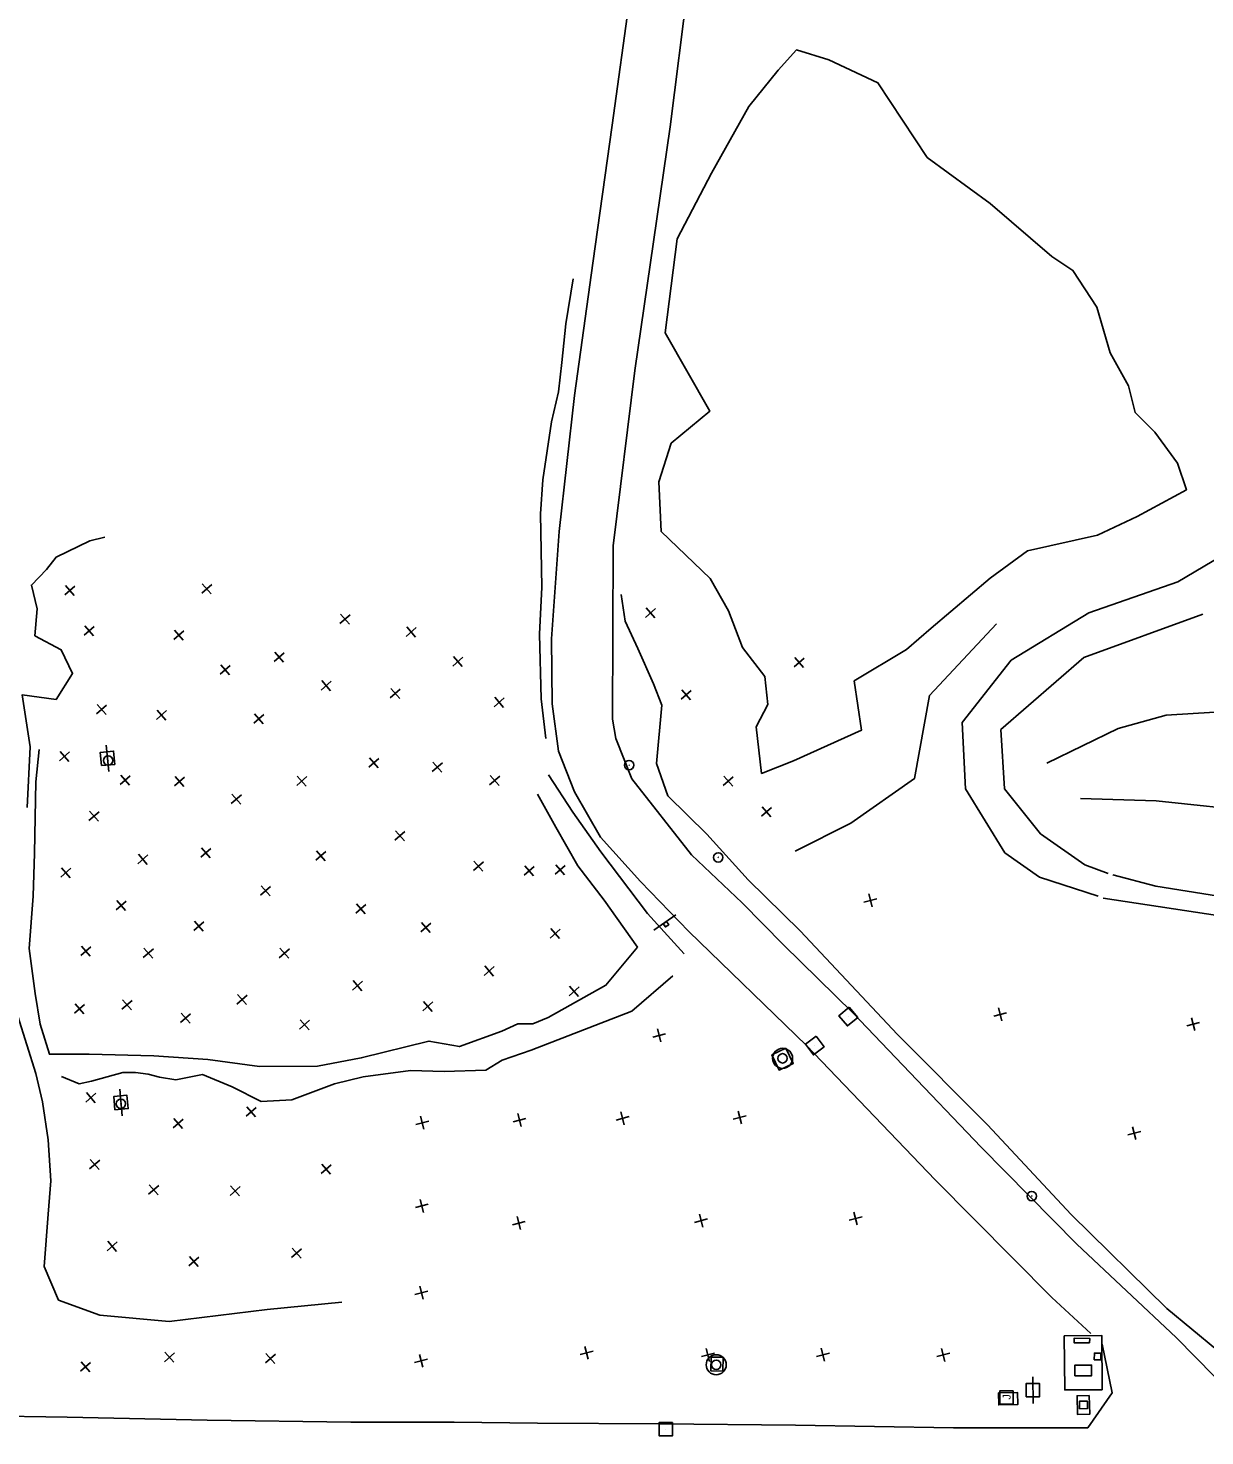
# Model space of a CAD drawing. Extents: x 4711259 to 4716401, y 890074 to 892728.
# Drawn here: x 4712145 to 4712586, y 891911 to 892439 of the extents above; entities that cross this region are included whole.
import ezdxf

# ---------------------------------------------------------------- set-up
doc = ezdxf.new("R2010")
doc.units = 0
for name, color, linetype in [('E_HY_STORM_Inlet', 7, 'Continuous'), ('E_HY_STORM_MH', 7, 'Continuous'), ('E_RDWY_ROAD_EdgeAsph', 7, 'Continuous'), ('E_RDWY_ROAD_EdgeConc', 7, 'Continuous'), ('E_RDWY_ROAD_EdgeGravel', 7, 'Continuous'), ('E_TERR_DTM_BrkLines', 7, 'Continuous'), ('E_TERR_DTM_RandomPt', 7, 'Continuous'), ('E_TRAF_SIGN_PrivateSign', 7, 'Continuous'), ('E_UTIL_ELEC_GENERAL', 7, 'Continuous'), ('E_UTIL_ELEC_POLE', 7, 'Continuous'), ('E_UTIL_MISC_General', 7, 'Continuous')]:
    doc.layers.add(name, color=color, linetype=linetype)

msp = doc.modelspace()

# ---------------------------------------------------------------- linework, layer by layer
at = {"layer": 'E_HY_STORM_Inlet'}
for p, q in [((4712452.77, 892068.62), (4712452.77, 892068.62)), ((4712440.17, 892057.77), (4712440.17, 892057.77)), ((4712384.34, 891913.98), (4712384.34, 891913.98))]:
    msp.add_line(p, q, dxfattribs=at)
for points in [[(4712453.09, 892072.14), (4712456.29, 892068.3), (4712452.45, 892065.1), (4712449.25, 892068.94)], [(4712440.65, 892061.28), (4712443.68, 892057.3), (4712439.7, 892054.27), (4712436.67, 892058.25)], [(4712386.81, 891916.51), (4712386.87, 891911.51), (4712381.87, 891911.45), (4712381.81, 891916.45)]]:
    msp.add_lwpolyline(points, close=True, dxfattribs=at)
at = {"layer": 'E_HY_STORM_MH'}
for centre, radius in [((4712428.12, 892052.97), 3.75), ((4712428.12, 892052.97), 1.76), ((4712403.22, 891938.11), 3.75), ((4712403.22, 891938.11), 1.76)]:
    msp.add_circle(centre, radius, dxfattribs=at)
at = {"layer": 'E_RDWY_ROAD_EdgeAsph'}
for points in [[(4712392.98, 892100.57), (4712374.85, 892119.26), (4712359.79, 892135.87), (4712350.09, 892152.92), (4712344.08, 892168.12), (4712341.64, 892185.83), (4712341.4, 892210.27), (4712344.38, 892250.53), (4712350.11, 892301.49), (4712356.98, 892351.1), (4712364.23, 892402.81), (4712370.85, 892450.92), (4712379.56, 892517.79), (4712388.22, 892587.46), (4712389.9, 892600.3)], [(4712411.53, 892596.72), (4712406.74, 892563.84), (4712398.3, 892499.3), (4712392.59, 892454.74), (4712385.98, 892402.12), (4712379.7, 892359.09), (4712372.74, 892310.83), (4712364.63, 892245.09), (4712364.34, 892180.15), (4712365.6, 892172.88), (4712371.63, 892157.7), (4712393.89, 892129.21), (4712412.91, 892111.29)], [(4712611.49, 891911.96), (4712575.66, 891948.29), (4712538.41, 891983.36), (4712502.63, 892019.7), (4712473.24, 892050.46), (4712454.51, 892069.97), (4712428.44, 892095.53), (4712412.91, 892111.29)], [(4712392.98, 892100.57), (4712437.09, 892057.82)], [(4712437.09, 892057.82), (4712485.27, 892007.48), (4712529.12, 891963.34), (4712543.72, 891949.78)], [(4712547.94, 891945.86), (4712551.69, 891927.6), (4712542.54, 891914.41), (4712492.24, 891914.44), (4712432.99, 891915.41), (4712382.1, 891915.95)], [(4712266.21, 891916.53), (4712212.37, 891917.36), (4712159.79, 891918.41), (4712127.55, 891918.93)], [(4712266.21, 891916.53), (4712304.99, 891916.54)], [(4712382.1, 891915.95), (4712336.14, 891916.18), (4712304.99, 891916.54)]]:
    msp.add_lwpolyline(points, dxfattribs=at)
at = {"layer": 'E_RDWY_ROAD_EdgeConc'}
for points in [[(4712429.38, 892056.77), (4712432.09, 892051.05), (4712426.81, 892048.55), (4712424.1, 892054.27)], [(4712533.77, 891949), (4712533.91, 891928.64), (4712547.95, 891928.74), (4712547.8, 891949.1)], [(4712401.36, 891940.99), (4712401.26, 891935.77), (4712405.72, 891935.69), (4712405.82, 891940.91)], [(4712509.11, 891927.56), (4712509.16, 891923.05), (4712516.3, 891923.14), (4712516.24, 891927.65)], [(4712543.13, 891926.59), (4712543.28, 891919.56), (4712538.68, 891919.47), (4712538.54, 891926.5)]]:
    msp.add_lwpolyline(points, close=True, dxfattribs=at)
at = {"layer": 'E_RDWY_ROAD_EdgeGravel'}
for points in [[(4712651.98, 892011.81), (4712651.97, 892011.81), (4712639.35, 892032.8), (4712635.99, 892051.36), (4712635.99, 892063.8), (4712634.48, 892083.04), (4712623.92, 892102.34), (4712600.26, 892112.35), (4712568.04, 892117.52), (4712551.95, 892121.72)], [(4712548.39, 892113.07), (4712595.33, 892105.89), (4712618.97, 892096.38), (4712626.83, 892078.05), (4712627.02, 892062.56), (4712629.02, 892036.67), (4712637.35, 892015.83), (4712646.12, 892006.34)]]:
    msp.add_lwpolyline(points, dxfattribs=at)
at = {"layer": 'E_TERR_DTM_BrkLines'}
for points in [[(4712432.18, 892164.48), (4712420.26, 892159.79), (4712418.21, 892177.21), (4712422.52, 892185.67), (4712421.46, 892196.16), (4712413.1, 892206.99), (4712407.81, 892220.7), (4712400.91, 892232.82), (4712382.63, 892250.5), (4712381.72, 892269.09), (4712386.27, 892283.53), (4712400.79, 892295.52), (4712384.12, 892324.98), (4712388.62, 892360.17), (4712401.49, 892384.79), (4712415.49, 892409.75), (4712426.49, 892423.39), (4712433.37, 892430.99), (4712445.46, 892427.29), (4712463.85, 892418.72), (4712482.3, 892390.69), (4712505.97, 892373.38), (4712529.14, 892353.61), (4712537.01, 892348.34), (4712545.9, 892334.57), (4712551, 892317.51), (4712557.88, 892305.06), (4712560.31, 892295.13), (4712567.68, 892287.65), (4712576.27, 892276.05), (4712579.58, 892266.1), (4712561.12, 892256.12), (4712546.16, 892249.15), (4712519.99, 892243.18), (4712505.94, 892232.97), (4712483.86, 892214.17), (4712474.6, 892206.24), (4712454.97, 892194.44), (4712457.7, 892175.97), (4712432.18, 892164.48)], [(4712339.29, 892172.92), (4712337.59, 892187.77), (4712336.93, 892211.95), (4712337.78, 892229.57), (4712337.36, 892257.07), (4712338.19, 892269.78), (4712341.39, 892291.6), (4712344.04, 892302.85), (4712345.27, 892313.87), (4712346.79, 892328.36), (4712349.57, 892345.14)], [(4712144.82, 892147.01), (4712145.96, 892169.74), (4712142.91, 892189.2), (4712155.65, 892187.47), (4712161.85, 892197.25), (4712157.58, 892206.17), (4712147.72, 892211.39), (4712148.62, 892221.53), (4712146.44, 892230.36), (4712152.12, 892236.19), (4712155.66, 892240.87), (4712168.35, 892246.91), (4712173.97, 892248.37)], [(4712546.45, 892113.77), (4712524.47, 892120.93), (4712511.44, 892130.07), (4712496.7, 892154.02), (4712495.5, 892178.83), (4712513.86, 892202.27), (4712543.01, 892220.01), (4712576.35, 892231.61), (4712592.62, 892241.19)], [(4712399.71, 892137), (4712385.06, 892151.32), (4712380.83, 892163.48), (4712382.85, 892185.31), (4712379.72, 892193.38), (4712373.83, 892206.65), (4712369.02, 892216.88), (4712367.53, 892226.88)], [(4712585.76, 892219.47), (4712541.13, 892203.22), (4712509.96, 892176.19), (4712511.32, 892154.06), (4712524.79, 892137.18), (4712541.41, 892125.46), (4712550.27, 892122.23)], [(4712432.87, 892130.6), (4712453.75, 892141.12), (4712477.58, 892157.87), (4712483.26, 892188.93), (4712508.39, 892215.83)], [(4712527.2, 892163.66), (4712554.02, 892176.64), (4712571.96, 892181.61), (4712608.43, 892183.92), (4712629.84, 892177.13), (4712683.46, 892182.87), (4712727.45, 892167.89), (4712767.53, 892172.83)], [(4712149.3, 892168.76), (4712148.1, 892156.57), (4712147.59, 892129.91), (4712147.08, 892113.77), (4712145.57, 892094.19), (4712147.76, 892077.26), (4712149.65, 892065.74), (4712153.15, 892054.51), (4712168.02, 892054.52), (4712192.37, 892053.88), (4712212.55, 892052.55), (4712231.9, 892049.97), (4712253.67, 892050.04), (4712270.1, 892053.12), (4712295.45, 892059.45), (4712306.89, 892057.35), (4712322.79, 892063.11), (4712328.83, 892065.88), (4712334.42, 892065.87), (4712340.26, 892068.34)], [(4712340.37, 892159.24), (4712349.51, 892145.22), (4712360, 892130.39), (4712377.4, 892107.24), (4712391.21, 892092.13)], [(4712373.74, 892094.64), (4712361.22, 892112.26), (4712351.36, 892125.16), (4712343.02, 892139.63), (4712336.22, 892152.01)], [(4712750.46, 892108.86), (4712730.1, 892125.9), (4712687.22, 892140.73), (4712641.38, 892141.46), (4712608.28, 892145.28), (4712568.27, 892149.46), (4712539.83, 892150.37)], [(4712619.1, 891920.49), (4712572.27, 891959.19), (4712536.3, 891994.41), (4712505.02, 892028.08), (4712471.23, 892061.89), (4712434.73, 892100.76), (4712415.26, 892119.86), (4712399.71, 892137)], [(4712373.74, 892094.64), (4712361.86, 892080.36), (4712340.26, 892068.34)], [(4712333.85, 892056.08), (4712371.6, 892070.68), (4712386.95, 892083.84)], [(4712262.78, 891961.59), (4712234.78, 891958.84), (4712198.06, 891954.35), (4712172.03, 891956.7), (4712156.6, 891962.35), (4712151.24, 891974.89), (4712152.67, 891994.51), (4712153.68, 892007.02), (4712152.63, 892022.38), (4712150.59, 892036.69), (4712148.04, 892047.33), (4712141.36, 892068.82)], [(4712333.85, 892056.08), (4712323.01, 892052.26), (4712316.85, 892048.5), (4712301.18, 892048.01), (4712288.53, 892048.35), (4712270.85, 892046.06), (4712260.09, 892043.47), (4712244.1, 892037.45), (4712232.63, 892036.82), (4712221.68, 892042.3), (4712210.6, 892046.9), (4712200.54, 892044.93), (4712194.43, 892045.91), (4712190.23, 892047.08), (4712185.46, 892047.61), (4712180.66, 892047.61), (4712168.93, 892044.46), (4712164.37, 892043.47), (4712157.7, 892046.18)]]:
    msp.add_lwpolyline(points, dxfattribs=at)
at = {"layer": 'E_TERR_DTM_RandomPt'}
for p, q in [((4712162.68, 892230.02), (4712158.92, 892226.73)), ((4712162.45, 892226.49), (4712159.15, 892230.25)), ((4712214.02, 892230.66), (4712210.26, 892227.36)), ((4712213.79, 892227.13), (4712210.5, 892230.89)), ((4712265.9, 892219.25), (4712262.13, 892215.96)), ((4712265.66, 892215.73), (4712262.37, 892219.49)), ((4712380.45, 892221.57), (4712376.68, 892218.28)), ((4712380.21, 892218.05), (4712376.92, 892221.81)), ((4712169.97, 892214.85), (4712166.2, 892211.56)), ((4712169.73, 892211.32), (4712166.44, 892215.08)), ((4712203.6, 892213.28), (4712199.84, 892209.99)), ((4712203.36, 892209.75), (4712200.07, 892213.51)), ((4712290.68, 892214.44), (4712286.91, 892211.15)), ((4712290.44, 892210.92), (4712287.15, 892214.68)), ((4712241.18, 892204.98), (4712237.41, 892201.69)), ((4712240.94, 892201.45), (4712237.65, 892205.22)), ((4712308.16, 892203.33), (4712304.4, 892200.04)), ((4712307.93, 892199.8), (4712304.64, 892203.57)), ((4712436.22, 892203.02), (4712432.45, 892199.73)), ((4712435.98, 892199.49), (4712432.69, 892203.26)), ((4712220.95, 892200.22), (4712217.18, 892196.93)), ((4712220.71, 892196.7), (4712217.42, 892200.46)), ((4712258.8, 892194.33), (4712255.04, 892191.04)), ((4712258.57, 892190.8), (4712255.28, 892194.56)), ((4712284.75, 892191.41), (4712280.98, 892188.12)), ((4712284.51, 892187.89), (4712281.22, 892191.65)), ((4712323.7, 892188.08), (4712319.94, 892184.79)), ((4712323.47, 892184.55), (4712320.17, 892188.32)), ((4712393.87, 892190.91), (4712390.11, 892187.62)), ((4712393.63, 892187.39), (4712390.34, 892191.15)), ((4712174.62, 892185.42), (4712170.86, 892182.12)), ((4712174.39, 892181.89), (4712171.09, 892185.65)), ((4712197.1, 892183.31), (4712193.34, 892180.01)), ((4712196.86, 892179.78), (4712193.57, 892183.54)), ((4712233.58, 892181.86), (4712229.81, 892178.57)), ((4712233.34, 892178.33), (4712230.05, 892182.09)), ((4712160.71, 892167.81), (4712156.94, 892164.52)), ((4712160.47, 892164.28), (4712157.18, 892168.05)), ((4712276.68, 892165.38), (4712272.91, 892162.09)), ((4712276.44, 892161.86), (4712273.15, 892165.62)), ((4712300.52, 892163.73), (4712296.76, 892160.44)), ((4712300.29, 892160.21), (4712297, 892163.97)), ((4712183.49, 892158.92), (4712179.73, 892155.63)), ((4712183.25, 892155.39), (4712179.96, 892159.16)), ((4712203.86, 892158.37), (4712200.1, 892155.08)), ((4712203.62, 892154.85), (4712200.33, 892158.61)), ((4712249.66, 892158.57), (4712245.89, 892155.28)), ((4712249.42, 892155.04), (4712246.13, 892158.81)), ((4712322.03, 892158.78), (4712318.26, 892155.48)), ((4712321.79, 892155.25), (4712318.5, 892159.01)), ((4712409.64, 892158.53), (4712405.88, 892155.24)), ((4712409.41, 892155.01), (4712406.12, 892158.77)), ((4712225.15, 892151.76), (4712221.38, 892148.47)), ((4712224.91, 892148.23), (4712221.62, 892151.99)), ((4712171.76, 892145.37), (4712168, 892142.08)), ((4712171.53, 892141.84), (4712168.24, 892145.61)), ((4712423.95, 892147), (4712420.19, 892143.71)), ((4712423.71, 892143.47), (4712420.42, 892147.23)), ((4712286.5, 892138.06), (4712282.73, 892134.77)), ((4712286.26, 892134.54), (4712282.97, 892138.3)), ((4712190.09, 892129.21), (4712186.33, 892125.92)), ((4712189.85, 892125.68), (4712186.56, 892129.45)), ((4712213.73, 892131.63), (4712209.97, 892128.34)), ((4712213.5, 892128.1), (4712210.21, 892131.86)), ((4712256.81, 892130.55), (4712253.05, 892127.26)), ((4712256.57, 892127.02), (4712253.28, 892130.78)), ((4712161.2, 892124.2), (4712157.43, 892120.91)), ((4712160.96, 892120.67), (4712157.67, 892124.43)), ((4712315.9, 892126.65), (4712312.14, 892123.36)), ((4712315.67, 892123.12), (4712312.38, 892126.88)), ((4712334.92, 892124.92), (4712331.16, 892121.63)), ((4712334.69, 892121.39), (4712331.39, 892125.16)), ((4712346.59, 892125.3), (4712342.83, 892122.01)), ((4712346.36, 892121.78), (4712343.07, 892125.54)), ((4712236.13, 892117.37), (4712232.36, 892114.08)), ((4712235.89, 892113.85), (4712232.6, 892117.61)), ((4712461.68, 892109.77), (4712460.41, 892114.61)), ((4712181.93, 892111.88), (4712178.16, 892108.59)), ((4712181.69, 892108.35), (4712178.4, 892112.11)), ((4712271.83, 892110.66), (4712268.06, 892107.37)), ((4712271.59, 892107.13), (4712268.3, 892110.9)), ((4712458.63, 892111.55), (4712463.46, 892112.82)), ((4712211.06, 892104.13), (4712207.3, 892100.84)), ((4712210.83, 892100.6), (4712207.54, 892104.37)), ((4712296.22, 892103.67), (4712292.45, 892100.38)), ((4712295.98, 892100.14), (4712292.69, 892103.91)), ((4712344.68, 892101.37), (4712340.92, 892098.08)), ((4712344.45, 892097.85), (4712341.16, 892101.61)), ((4712168.71, 892094.77), (4712164.94, 892091.48)), ((4712168.47, 892091.24), (4712165.18, 892095.01)), ((4712192.13, 892094.07), (4712188.37, 892090.78)), ((4712191.9, 892090.54), (4712188.61, 892094.31)), ((4712243.15, 892093.98), (4712239.38, 892090.69)), ((4712242.91, 892090.46), (4712239.62, 892094.22)), ((4712319.93, 892087.35), (4712316.16, 892084.06)), ((4712319.69, 892083.83), (4712316.4, 892087.59)), ((4712270.56, 892081.86), (4712266.8, 892078.57)), ((4712270.32, 892078.33), (4712267.03, 892082.1)), ((4712227.26, 892076.63), (4712223.49, 892073.33)), ((4712227.02, 892073.1), (4712223.73, 892076.86)), ((4712351.78, 892079.74), (4712348.02, 892076.45)), ((4712351.55, 892076.21), (4712348.26, 892079.98)), ((4712166.29, 892073.13), (4712162.53, 892069.84)), ((4712166.06, 892069.6), (4712162.77, 892073.37)), ((4712184.13, 892074.67), (4712180.37, 892071.38)), ((4712183.9, 892071.15), (4712180.61, 892074.91)), ((4712296.97, 892074.1), (4712293.21, 892070.81)), ((4712296.74, 892070.57), (4712293.44, 892074.33)), ((4712510.36, 892067.01), (4712509.09, 892071.85)), ((4712206.13, 892069.71), (4712202.36, 892066.42)), ((4712205.89, 892066.18), (4712202.6, 892069.95)), ((4712250.75, 892067.22), (4712246.99, 892063.93)), ((4712250.51, 892063.69), (4712247.22, 892067.45)), ((4712507.31, 892068.8), (4712512.14, 892070.07)), ((4712579.66, 892065.16), (4712584.49, 892066.43)), ((4712582.71, 892063.38), (4712581.44, 892068.21)), ((4712379.42, 892060.93), (4712384.25, 892062.2)), ((4712382.47, 892059.15), (4712381.2, 892063.98)), ((4712170.54, 892039.86), (4712166.77, 892036.57)), ((4712170.3, 892036.33), (4712167.01, 892040.1)), ((4712230.66, 892034.54), (4712226.9, 892031.25)), ((4712230.43, 892031.01), (4712227.14, 892034.77)), ((4712203.31, 892030.19), (4712199.55, 892026.9)), ((4712203.08, 892026.66), (4712199.79, 892030.43)), ((4712290.56, 892028.18), (4712295.4, 892029.46)), ((4712293.61, 892026.4), (4712292.34, 892031.24)), ((4712327.04, 892029.19), (4712331.88, 892030.46)), ((4712330.1, 892027.41), (4712328.83, 892032.25)), ((4712365.68, 892029.85), (4712370.52, 892031.12)), ((4712368.74, 892028.06), (4712367.46, 892032.9)), ((4712409.64, 892030.15), (4712414.48, 892031.42)), ((4712412.69, 892028.37), (4712411.42, 892033.2)), ((4712557.57, 892024.29), (4712562.41, 892025.56)), ((4712560.63, 892022.51), (4712559.36, 892027.34)), ((4712172.02, 892014.81), (4712168.25, 892011.52)), ((4712171.78, 892011.29), (4712168.49, 892015.05)), ((4712258.82, 892013.08), (4712255.05, 892009.79)), ((4712258.58, 892009.55), (4712255.29, 892013.31)), ((4712194.14, 892005.29), (4712190.37, 892002)), ((4712193.9, 892001.76), (4712190.61, 892005.53)), ((4712224.65, 892004.9), (4712220.89, 892001.61)), ((4712224.42, 892001.37), (4712221.13, 892005.13)), ((4712290.39, 891996.99), (4712295.23, 891998.26)), ((4712293.44, 891995.21), (4712292.17, 892000.05)), ((4712326.79, 891990.56), (4712331.63, 891991.83)), ((4712329.85, 891988.78), (4712328.58, 891993.62)), ((4712395.13, 891991.47), (4712399.97, 891992.74)), ((4712398.19, 891989.69), (4712396.91, 891994.52)), ((4712453.06, 891992.28), (4712457.9, 891993.56)), ((4712456.12, 891990.5), (4712454.85, 891995.34)), ((4712178.57, 891984.14), (4712174.81, 891980.85)), ((4712178.34, 891980.61), (4712175.05, 891984.38)), ((4712247.75, 891981.57), (4712243.98, 891978.28)), ((4712247.51, 891978.05), (4712244.22, 891981.81)), ((4712209.19, 891978.49), (4712205.43, 891975.2)), ((4712208.96, 891974.96), (4712205.66, 891978.73)), ((4712290.25, 891964.46), (4712295.09, 891965.73)), ((4712293.31, 891962.68), (4712292.04, 891967.52)), ((4712355.25, 891940.14), (4712353.98, 891944.98)), ((4712400.76, 891939.36), (4712399.49, 891944.2)), ((4712443.87, 891939.42), (4712442.59, 891944.26)), ((4712488.99, 891939.37), (4712487.72, 891944.2)), ((4712168.56, 891938.97), (4712164.8, 891935.68)), ((4712168.33, 891935.44), (4712165.03, 891939.21)), ((4712200.02, 891942.54), (4712196.26, 891939.25)), ((4712199.78, 891939.01), (4712196.49, 891942.77)), ((4712237.91, 891942.08), (4712234.14, 891938.79)), ((4712237.67, 891938.56), (4712234.38, 891942.32)), ((4712290.11, 891938.93), (4712294.95, 891940.2)), ((4712293.16, 891937.14), (4712291.89, 891941.98)), ((4712352.19, 891941.92), (4712357.03, 891943.2)), ((4712397.71, 891941.14), (4712402.55, 891942.41)), ((4712440.81, 891941.21), (4712445.65, 891942.48)), ((4712485.93, 891941.15), (4712490.77, 891942.42))]:
    msp.add_line(p, q, dxfattribs=at)
at = {"layer": 'E_TRAF_SIGN_PrivateSign'}
for p, q in [((4712379.83, 892101.03), (4712388.06, 892106.71)), ((4712384.37, 892103.25), (4712384.37, 892103.25))]:
    msp.add_line(p, q, dxfattribs=at)
msp.add_lwpolyline([(4712383.33, 892103.44), (4712384.18, 892102.21), (4712385.42, 892103.06), (4712384.56, 892104.3)], close=True, dxfattribs=at)
at = {"layer": 'E_UTIL_ELEC_GENERAL'}
msp.add_lwpolyline([(4712514.59, 891928.35), (4712514.57, 891923.35), (4712509.57, 891923.38), (4712509.59, 891928.38)], close=True, dxfattribs=at)
at = {"layer": 'E_UTIL_ELEC_POLE'}
for p, q in [((4712175.43, 892160.44), (4712174.48, 892170.39)), ((4712180.48, 892031.4), (4712179.52, 892041.35)), ((4712522.03, 891923.55), (4712521.91, 891933.55))]:
    msp.add_line(p, q, dxfattribs=at)
for points in [[(4712172.71, 892162.69), (4712172.23, 892167.66), (4712177.21, 892168.14), (4712177.68, 892163.16)], [(4712177.75, 892033.65), (4712177.27, 892038.63), (4712182.25, 892039.1), (4712182.73, 892034.13)], [(4712519.5, 891926.02), (4712519.44, 891931.02), (4712524.44, 891931.08), (4712524.5, 891926.08)]]:
    msp.add_lwpolyline(points, close=True, dxfattribs=at)
at = {"layer": 'E_UTIL_MISC_General'}
for p, q in [((4712174.99, 892164.65), (4712175.28, 892164.57)), ((4712175.09, 892164.46), (4712175.18, 892164.76)), ((4712370.66, 892163.03), (4712370.45, 892162.8)), ((4712370.45, 892163.02), (4712370.67, 892162.81)), ((4712403.89, 892128.43), (4712404.11, 892128.22)), ((4712404.11, 892128.44), (4712403.9, 892128.21)), ((4712179.78, 892035.97), (4712180.07, 892035.89)), ((4712179.88, 892035.78), (4712179.97, 892036.08)), ((4712521.44, 892001.47), (4712521.67, 892001.26)), ((4712521.66, 892001.48), (4712521.45, 892001.25))]:
    msp.add_line(p, q, dxfattribs=at)
for points in [[(4712543.25, 891946.26), (4712537.4, 891946.34), (4712537.42, 891948.04), (4712543.28, 891947.96)], [(4712545.01, 891939.96), (4712547.43, 891939.9), (4712547.5, 891942.42), (4712545.08, 891942.49)], [(4712537.77, 891933.98), (4712543.98, 891933.97), (4712543.98, 891937.98), (4712537.77, 891937.99)], [(4712539.45, 891921.61), (4712542.45, 891921.64), (4712542.41, 891924.43), (4712539.42, 891924.39)]]:
    msp.add_lwpolyline(points, close=True, dxfattribs=at)
for centre in [(4712175.16, 892164.62), (4712370.56, 892162.88), (4712404, 892128.29), (4712179.95, 892035.94), (4712521.56, 892001.33)]:
    msp.add_circle(centre, 1.75, dxfattribs=at)

# ---------------------------------------------------------------- texts
at = {"layer": 'E_UTIL_ELEC_GENERAL'}
msp.add_text('J', height=3, rotation=89.688, dxfattribs=at).set_placement((4712513.64, 891925.01))

doc.saveas('drawing.dxf')
